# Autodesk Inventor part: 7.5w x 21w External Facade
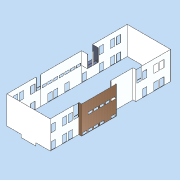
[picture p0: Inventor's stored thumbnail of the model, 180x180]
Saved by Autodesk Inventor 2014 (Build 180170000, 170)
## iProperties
Created: 2012-07
Part Number: 7.5w x 21w External Facade
Document SubType Name: Modeling
Designer: david.appleford
Mass: 7.63356e+06 g
Surface Area: 7.71188e+06 cm^2
Volume: 7.63356e+06 cm^3
Density: 1 g/cm^3
Cost Center: REF
Description: External Facade
Material: Generic
Appearance: Snow
Justset: False
Author: david.appleford
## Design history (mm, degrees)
sketch "Sketch1"
  geometry: L1 (6, -567)-(6, 565) reference; L2 (-78, 649)-(-600, 649) reference; L3 (-9140, -25051)-(-8008, -25051) reference; L4 (-9224, -23835)-(-9224, -24967) reference; L5 (616, -12767)-(616, -11635) reference; L6 (532, -11551)-(424, -11551) reference; L7 (616, -18867)-(616, -17735) reference; L8 (10, -18951)-(532, -18951) reference; L9 (-600, -6751)-(-78, -6751) reference; L10 (-604, -7887)-(-604, -6755) reference; L11 (-492, -11551)-(418, -11551) reference; L12 (-9224, -25051)-(6, -25051); L13 (6, 649)-(-9224, 649); L14 (-9224, 649)-(-9224, -25051); L15 (6, -6751)-(-604, -6751); L16 (-604, -6751)-(-604, -11551); L17 (-604, -11551)-(6, -11551); L18 (6, -11551)-(616, -11551); L19 (616, -11551)-(616, -18951); L20 (616, -18951)-(6, -18951); L21 (6, -25051)-(6, -18951); L22 (6, -6751)-(6, 649); L23 (-584, -11531)-(-584, -6771); L24 (-584, -6771)-(26, -6771); L25 (26, -6771)-(26, 669); L26 (26, 669)-(-9244, 669); L27 (-9244, 669)-(-9244, -25071); L28 (-9244, -25071)-(26, -25071); L29 (26, -25071)-(26, -18971); L30 (26, -18971)-(636, -18971); L31 (636, -18971)-(636, -11531); L32 (636, -11531)-(6, -11531); L33 (6, -11531)-(-584, -11531); 1 further point
  constraints: 44 end point, 3 collinear, 1 point on line, 10 other
  dimensions: "d0" = 20 distance between parallel lines of L13 L26
  node "Reference1"
  node "Reference2"
  node "Reference3"
  node "Reference4"
  node "Reference5"
  node "Reference6"
  node "Reference7"
  node "Reference8"
  node "Reference9"
  node "Reference10"
  node "Reference11"
workplane "Work Plane1"
extrude "Extrusion1" new body sketch "Sketch1" stored distance "d1" = 10; taper "d2" = 0 deg
sketch "Sketch2"
  geometry: L1 (2668, 6015)-(2668, 5085) reference; L2 (2668, 5085)-(1138, 5085) reference; L3 (1138, 6015)-(2668, 6015) reference; L4 (1138, 5085)-(1138, 6015) reference; L5 (2668, 4795)-(2668, 3865) reference; L6 (1138, 4795)-(2668, 4795) reference; L7 (2668, 3865)-(1138, 3865) reference; L8 (1138, 3865)-(1138, 4795) reference; L9 (2668, 2355)-(2668, 1425) reference; L10 (1138, 2355)-(2668, 2355) reference; L11 (2668, 1425)-(1138, 1425) reference; L12 (1138, 1425)-(1138, 2355) reference; L13 (2664, 1135)-(2664, 205) reference; L14 (2184, 1135)-(2664, 1135) reference; L15 (2664, 205)-(2184, 205) reference; L16 (2184, 205)-(2184, 1135) reference; L17 (2111, 205)-(2111, 1141) reference; L18 (77, 205)-(2111, 205) reference; L19 (2111, 1141)-(77, 1141) reference; L20 (5877, 6015)-(5877, 5085) reference; L21 (4347, 6015)-(5877, 6015) reference; L22 (5877, 5085)-(4347, 5085) reference; L23 (4347, 5085)-(4347, 6015) reference; L24 (4347, 3865)-(4347, 4795) reference; L25 (4347, 4795)-(5877, 4795) reference; L26 (5877, 3865)-(4347, 3865) reference; L27 (5877, 4795)-(5877, 3865) reference; L28 (5877, 2355)-(5877, 1425) reference; L29 (5877, 1425)-(4347, 1425) reference; L30 (4347, 2355)-(5877, 2355) reference; L31 (4347, 1425)-(4347, 2355) reference; L32 (5877, -13505)-(5877, -14435) reference; L33 (5877, -14435)-(4347, -14435) reference; L34 (4347, -13505)-(5877, -13505) reference; L35 (4347, -14435)-(4347, -13505) reference; L36 (4347, -14725)-(5877, -14725) reference; L37 (5877, -14725)-(5877, -15655) reference; L38 (5877, -15655)-(4347, -15655) reference; L39 (4347, -15655)-(4347, -14725) reference; L40 (4347, -15945)-(5877, -15945) reference; L41 (5877, -15945)-(5877, -16875) reference; L42 (5877, -16875)-(4347, -16875) reference; L43 (4347, -16875)-(4347, -15945) reference; L44 (5877, -17165)-(5877, -18095) reference; L45 (4347, -17165)-(5877, -17165) reference; L46 (5877, -18095)-(4347, -18095) reference; L47 (4347, -18095)-(4347, -17165) reference; L48 (2668, -17165)-(2668, -18095) reference; L49 (2668, -18095)-(1138, -18095) reference; L50 (1138, -17165)-(2668, -17165) reference; L51 (1138, -18095)-(1138, -17165) reference; L52 (2668, -14725)-(2668, -15655) reference; L53 (1138, -14725)-(2668, -14725) reference; L54 (2668, -15655)-(1138, -15655) reference; L55 (1138, -15655)-(1138, -14725) reference; L56 (1138, -14435)-(1138, -13505) reference; L57 (2668, -13505)-(2668, -14435) reference; L58 (2668, -14435)-(1138, -14435) reference; L59 (1138, -13505)-(2668, -13505) reference; L60 (2664, -12285)-(2664, -13215) reference; L61 (2664, -13215)-(2184, -13215) reference; L62 (2184, -13215)-(2184, -12285) reference; L63 (2184, -12285)-(2664, -12285) reference; L64 (2111, -13215)-(2111, -12279) reference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; 1 further point
  constraints: 18 end point, 3 point on line
extrude "Extrusion2" cut sketch "Sketch2" distance "d3" = 20; taper "d4" = 0 deg
sketch "Sketch3"
  geometry: L1 (5873, 6305)-(5393, 6305) reference; L2 (5873, 7235)-(5873, 6305) reference; L3 (5393, 7235)-(5873, 7235) reference; L4 (5393, 6305)-(5393, 7235) reference; L5 (5393, 6015)-(5873, 6015) reference; L6 (5873, 6015)-(5873, 5085) reference; L7 (5873, 5085)-(5393, 5085) reference; L8 (5393, 5085)-(5393, 6015) reference; L9 (5393, 4795)-(5873, 4795) reference; L10 (5873, 4795)-(5873, 3865) reference; L11 (5873, 3865)-(5393, 3865) reference; L12 (5393, 3865)-(5393, 4795) reference; L13 (5393, 3575)-(5873, 3575) reference; L14 (5873, 3575)-(5873, 2645) reference; L15 (5873, 2645)-(5393, 2645) reference; L16 (5393, 2645)-(5393, 3575) reference; L17 (5393, 2355)-(5873, 2355) reference; L18 (5873, 2355)-(5873, 1425) reference; L19 (5873, 1425)-(5393, 1425) reference; L20 (5393, 1425)-(5393, 2355) reference; L21 (5393, 1135)-(5873, 1135) reference; L22 (5873, 1135)-(5873, 205) reference; L23 (5873, 205)-(5393, 205) reference; L24 (5393, 205)-(5393, 1135) reference; L25 (2184, 7235)-(2664, 7235) reference; L26 (2664, 7235)-(2664, 6305) reference; L27 (2664, 6305)-(2184, 6305) reference; L28 (2184, 6305)-(2184, 7235) reference; L29 (2184, 6015)-(2664, 6015) reference; L30 (2664, 6015)-(2664, 5085) reference; L31 (2664, 5085)-(2184, 5085) reference; L32 (2184, 5085)-(2184, 6015) reference; L33 (2664, 4795)-(2664, 3865) reference; L34 (2184, 4795)-(2664, 4795) reference; L35 (2184, 3865)-(2184, 4795) reference; L36 (2664, 3865)-(2184, 3865) reference; L37 (2184, 3575)-(2664, 3575) reference; L38 (2664, 3575)-(2664, 2645) reference; L39 (2664, 2645)-(2184, 2645) reference; L40 (2184, 2645)-(2184, 3575) reference; L41 (2184, 2355)-(2664, 2355) reference; L42 (2664, 2355)-(2664, 1425) reference; L43 (2664, 1425)-(2184, 1425) reference; L44 (2184, 1425)-(2184, 2355) reference; 1 further point
extrude "Extrusion3" cut sketch "Sketch3" distance "d5" = 20; taper "d6" = 0 deg
sketch "Sketch4"
  geometry: L1 (85, 2664)-(1015, 2664) reference; L2 (85, 2184)-(85, 2664) reference; L3 (1015, 2664)-(1015, 2184) reference; L4 (1015, 2184)-(85, 2184) reference; L5 (1015, 2111)-(79, 2111) reference; L6 (79, 2111)-(79, 77) reference; L7 (1015, 77)-(1015, 2111) reference; L8 (1015, 77)-(79, 77); L9 (1116, 66.469)-(1116, 78) reference; L10 (-16, 78)-(1116, 78) reference; L11 (-16, 66.469)-(-16, 78) reference; L12 (-16, 66.469)-(1116, 66.469) reference; L13 (1116, -6)-(1116, 47.141) reference; L14 (-16, 47.141)-(1116, 47.141) reference; L15 (-16, -6)-(-16, 47.141) reference; L16 (-16, -6)-(1116, -6) reference; L17 (1116, -6)-(-16, -6); L18 (-16, -6)-(-16, 78); L19 (1116, 78)-(1116, -6); L20 (-16, 78)-(79, 78); L21 (1015, 78)-(1116, 78); 1 further point
  constraints: 12 end point, 2 point on line
extrude "Extrusion4" cut sketch "Sketch4" distance "d7" = 20; taper "d8" = 0 deg
sketch "Sketch5"
  geometry: L1 (-5877, 1425)-(-5877, 2355) reference; L2 (-4347, 1425)-(-5877, 1425) reference; L3 (-5877, 2355)-(-4347, 2355) reference; L4 (-4347, 2355)-(-4347, 1425); L5 (-5877, 2645)-(-5877, 3575) reference; L6 (-4347, 2645)-(-5877, 2645) reference; L7 (-5877, 3575)-(-4347, 3575) reference; L8 (-4347, 3575)-(-4347, 2645) reference; L9 (-5877, 5085)-(-5877, 6015) reference; L10 (-4347, 5085)-(-5877, 5085) reference; L11 (-5877, 6015)-(-4347, 6015) reference; L12 (-4347, 6015)-(-4347, 5085) reference; L13 (-2668, 1425)-(-2668, 2355) reference; L14 (-1138, 1425)-(-2668, 1425) reference; L15 (-2668, 2355)-(-1138, 2355) reference; L16 (-1138, 2355)-(-1138, 1425) reference; L17 (-1138, 2645)-(-2668, 2645) reference; L18 (-2668, 2645)-(-2668, 3575) reference; L19 (-2668, 3575)-(-1138, 3575) reference; L20 (-1138, 3575)-(-1138, 2645) reference; L21 (-2668, 5085)-(-2668, 6015) reference; L22 (-1138, 5085)-(-2668, 5085) reference; L23 (-2668, 6015)-(-1138, 6015) reference; L24 (-1138, 6015)-(-1138, 5085) reference; L25 (-2664, 6305)-(-2664, 7235) reference; L26 (-2664, 7235)-(-2184, 7235) reference; L27 (-2184, 7235)-(-2184, 6305) reference; L28 (-2184, 6305)-(-2664, 6305) reference; L29 (-2184, 7525)-(-2664, 7525) reference; L30 (-2664, 7525)-(-2664, 8455) reference; L31 (-2664, 8455)-(-2184, 8455) reference; L32 (-2184, 8455)-(-2184, 7525) reference; L33 (-2664, 8745)-(-2664, 9675) reference; L34 (-2664, 9675)-(-2184, 9675) reference; L35 (-2184, 9675)-(-2184, 8745) reference; L36 (-2184, 8745)-(-2664, 8745) reference; L37 (-2184, 9965)-(-2664, 9965) reference; L38 (-2664, 9965)-(-2664, 10895) reference; L39 (-2664, 10895)-(-2184, 10895) reference; L40 (-2184, 10895)-(-2184, 9965) reference; L41 (-2664, 12405)-(-2664, 13335) reference; L42 (-2664, 13335)-(-2184, 13335) reference; L43 (-2184, 13335)-(-2184, 12405) reference; L44 (-2184, 12405)-(-2664, 12405) reference; L45 (-2664, 11185)-(-2664, 12115) reference; L46 (-2184, 11185)-(-2664, 11185) reference; L47 (-2664, 12115)-(-2184, 12115) reference; L48 (-2184, 12115)-(-2184, 11185) reference; L49 (-2664, 13625)-(-2664, 14555) reference; L50 (-2664, 14555)-(-2184, 14555) reference; L51 (-2184, 14555)-(-2184, 13625) reference; L52 (-2184, 13625)-(-2664, 13625) reference; L53 (-2664, 14845)-(-2664, 15775) reference; L54 (-2184, 14845)-(-2664, 14845) reference; L55 (-2664, 15775)-(-2184, 15775) reference; L56 (-2184, 15775)-(-2184, 14845) reference; L57 (-2668, 19725)-(-2668, 20655) reference; L58 (-1138, 19725)-(-2668, 19725) reference; L59 (-2668, 20655)-(-1138, 20655) reference; L60 (-1138, 20655)-(-1138, 19725) reference; L61 (-5877, 16065)-(-5877, 16995) reference; L62 (-4347, 16065)-(-5877, 16065) reference; L63 (-5877, 16995)-(-4347, 16995) reference; L64 (-4347, 16995)-(-4347, 16065) reference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; 1 further point
  constraints: 14 end point, 2 point on line
extrude "Extrusion5" cut sketch "Sketch5" distance "d9" = 20; taper "d10" = 0 deg
sketch "Sketch6"
  geometry: L1 (5870, 15960)-(3213, 15960) reference; L2 (3213, 18320)-(5870, 18320) reference; L3 (3212, 17190)-(3212, 18310) reference; L4 (3232, 15980)-(5948, 15980); L5 (5948, 15980)-(5948, 18300); L6 (5948, 18300)-(3232, 18300); L7 (3232, 18300)-(3232, 15980); L8 (5870, 17184)-(3213, 17184) reference; L9 (3213, 19536)-(5870, 19536) reference; L10 (5948, 25740)-(5948, 7336) reference; 1 further point
  constraints: 8 end point, 1 collinear
  dimensions: "d11" = 20 distance between parallel lines of L7 L3; "d16" = 20 distance between parallel lines of L4 L1; "d17" = 20 distance between parallel lines of L2 L6
extrude "Extrusion7" cut sketch "Sketch6" distance "d18" = 20; taper "d19" = 0 deg
sketch "Sketch7"
  geometry: L1 (-8004, -6755)-(-8004, -6863) reference; L2 (-8008, -9107)-(-8008, -7975) reference; L3 (-7998, -9117)-(-7930, -9117) reference; L4 (-7930, -8542)-(-7930, -9117) reference; L5 (-7930, -8542)-(-7998, -8542) reference; L6 (-7998, -8542)-(-7998, -9117) reference; L7 (-9244, -6771)-(-9224, -6771) reference; L8 (-9224, -9091)-(-9244, -9091) reference; L9 (-9224, -6771)-(-8024, -6771); L10 (-8024, -6771)-(-8024, -9091); L11 (-8024, -9091)-(-9224, -9091); L12 (-9224, -9111)-(-8004, -9111); L13 (-8004, -9111)-(-8004, -6751); L14 (-8004, -6751)-(-9224, -6751); L15 (-9224, -9111)-(-9224, -9091); L16 (-9224, -6771)-(-9224, -6751); 1 further point
  constraints: 16 end point, 2 collinear, 1 other
  dimensions: "d20" = 20 distance between parallel lines of L1 L10; "d23" = 20 distance between parallel lines of L11 L12; "d24" = 20 distance between parallel lines of L14 L9 (derived)
extrude "Extrusion8" join sketch "Sketch7" stored distance "d21" = 20; taper "d22" = 0 deg
sketch "Sketch8"
  geometry: L1 (1220, 0)-(20, 0) reference; L2 (1220, 2320)-(1220, 0) reference; L3 (20, 2320)-(20, 0) reference; L4 (0, 2320)-(1220, 2320) reference; L5 (0, 0)-(0, 2320) reference; 1 further point
extrude "Extrusion9" join sketch "Sketch8" distance "d25" = 20; taper "d26" = 0 deg
sketch "Sketch9"
  geometry: L1 (-2664, 85)-(-2664, 1015) reference; L2 (-2664, 1015)-(-2184, 1015) reference; L3 (-2184, 1015)-(-2184, 85) reference; L4 (-2184, 85)-(-2664, 85) reference; L5 (-2664, 1305)-(-2664, 2235) reference; L6 (-2184, 1305)-(-2664, 1305) reference; L7 (-2664, 2235)-(-2184, 2235) reference; L8 (-2184, 2235)-(-2184, 1305) reference; L9 (-2111, 1015)-(-2111, 79) reference; L10 (-77, 1015)-(-2111, 1015) reference; L11 (-2111, 79)-(-77, 79) reference; L12 (-2111, 2235)-(-2111, 1299) reference; L13 (-2111, 1299)-(-77, 1299) reference; L14 (-77, 2235)-(-2111, 2235) reference; L15 (-77, 79)-(-77, 1015); L16 (-77, 1299)-(-77, 2235); L17 (-78, -16)-(-78, 1116) reference; L18 (0, 2320)-(0, 0) reference; L19 (-78, -16)-(0, -16); L20 (0, -16)-(0, 2320); L21 (0, 2320)-(-78, 2320); L22 (-78, 2320)-(-78, 2235); L23 (-78, 1299)-(-78, -16); L24 (-66.469, 1116)-(-78, 1116) reference; L25 (-66.469, 1204)-(-78, 1204) reference; L26 (-78, 1116)-(0, 1116); L27 (-78, 1204)-(0, 1204); 1 further point
  constraints: 18 end point, 4 point on line
extrude "Extrusion10" cut sketch "Sketch9" distance "d27" = 20; taper "d28" = 0 deg
sketch "Sketch10"
  geometry: L1 (3076, 6027)-(3144, 6027) reference; L2 (3144, 6568)-(3144, 6027) reference; L3 (3144, 6568)-(3076, 6568) reference; L4 (3076, 6568)-(3076, 6027) reference; L5 (6126, 6026)-(6194, 6026) reference; L6 (6194, 6568)-(6194, 6026) reference; L7 (6194, 6568)-(6126, 6568) reference; L8 (6126, 6568)-(6126, 6026) reference; L9 (6250, 6558)-(6250, 6636) reference; L10 (6250, 6636)-(3076, 6636) reference; L11 (3076, 6636)-(3076, 6558) reference; L12 (3076, 6558)-(6250, 6558) reference; L13 (0, 5948)-(9270, 5948) reference; L14 (0, 0)-(0, 5948) reference; L15 (9270, 0)-(0, 0) reference; L16 (9270, 0)-(9270, 5948) reference; L17 (3076, 6558)-(6194, 6558); L18 (6194, 6558)-(6194, 5948); L19 (6194, 5948)-(3076, 5948); L20 (3076, 5948)-(3076, 6558); 1 further point
  constraints: 8 end point, 1 point on line
extrude "Extrusion11" join sketch "Sketch10" distance "d29" = 20; taper "d30" = 0 deg
sketch "Sketch11"
  geometry: L1 (9270, -5948)-(0, -5948) reference; L2 (9270, 0)-(9270, -5948) reference; L3 (0, 0)-(9270, 0) reference; L4 (0, 0)-(0, -5948) reference; L5 (6194, -6027)-(6126, -6027) reference; L6 (6126, -6568)-(6126, -6027) reference; L7 (6126, -6568)-(6194, -6568) reference; L8 (6194, -6568)-(6194, -6027) reference; L9 (6194, -6636)-(6194, -6558) reference; L10 (6194, -6558)-(3020, -6558) reference; L11 (3020, -6558)-(3020, -6636) reference; L12 (3020, -6636)-(6194, -6636) reference; L13 (3076, -6568)-(3144, -6568) reference; L14 (3144, -6026)-(3144, -6568) reference; L15 (3144, -6026)-(3076, -6026) reference; L16 (3076, -6026)-(3076, -6568) reference; L17 (6194, -6558)-(3076, -6558); L18 (3076, -6558)-(3076, -5948); L19 (3076, -5948)-(6194, -5948); L20 (6194, -5948)-(6194, -6558); 1 further point
  constraints: 8 end point, 1 point on line
extrude "Extrusion12" join sketch "Sketch11" distance "d31" = 20; taper "d32" = 0 deg
sketch "Sketch13"
  geometry: L1 (0, 7235)-(3284, 7235); L2 (3284, 7235)-(3284, 7236); L3 (3284, 7236)-(0, 7236); L4 (0, 7236)-(0, 7235); L5 (0, 15979)-(3232, 15979); L6 (3232, 15979)-(3232, 15980); L7 (3232, 15980)-(0, 15980); L8 (0, 15980)-(0, 15979); L9 (3284, 6305)-(3284, 7235) reference; L10 (0, 0)-(0, 25740) reference; L11 (3232, 15980)-(3232, 18300) reference; L12 (3764, 7235)-(3764, 6305) reference; L13 (3837, 6299)-(3837, 7235) reference; L14 (3764, 7235)-(3837, 7235); L15 (3837, 7235)-(3837, 7236); L16 (3837, 7236)-(3764, 7236); L17 (3764, 7236)-(3764, 7235); 1 further point
  constraints: 24 end point, 3 collinear
  dimensions: "d35" = 1 distance between parallel lines of L3 L1; "d36" = 1 distance between parallel lines of L7 L5
extrude "Extrusion14" cut sketch "Sketch13" distance "d37" = 1; taper "d38" = 0 deg
body "Solid1"
node "Reference12"
node "Reference13"
node "Reference14"
node "Reference15"
node "Reference16"
node "Reference17"
node "Reference18"
node "Reference19"
node "Reference20"
node "Reference21"
node "Reference22"
node "Reference23"
node "Reference24"
node "Reference25"
node "Reference26"
node "Reference27"
node "Reference28"
node "Reference29"
node "Reference30"
node "Reference31"
node "Reference32"
node "Reference33"
node "Reference34"
node "Reference35"
node "Reference36"
node "Reference37"
node "Reference38"
node "Reference39"
node "Reference40"
node "Reference41"
node "Reference42"
node "Reference43"
node "Reference44"
node "Reference45"
node "Reference46"
node "Reference47"
node "Reference48"
node "Reference49"
node "Reference50"
node "Reference51"
node "Reference52"
node "Reference53"
node "Reference54"
node "Reference55"
node "Reference56"
node "Reference57"
node "Reference58"
node "Reference59"
node "Reference60"
node "Reference61"
node "Reference62"
node "Reference63"
node "Reference64"
node "Reference65"
node "Reference66"
node "Reference67"
node "Reference68"
node "Reference69"
node "Reference70"
node "Reference71"
node "Reference72"
node "Reference73"
node "Reference74"
node "Reference75"
node "Reference76"
node "Reference77"
node "Reference78"
node "Reference79"
node "Reference80"
node "Reference81"
node "Reference82"
node "Reference83"
node "Reference84"
node "Reference85"
node "Reference86"
node "Reference87"
node "Reference88"
node "Reference89"
node "Reference90"
node "Reference91"
node "Reference92"
node "Reference93"
node "Reference94"
node "Reference95"
node "Reference96"
node "Reference97"
node "Reference98"
node "Reference99"
node "Reference100"
node "Reference101"
node "Reference102"
node "Reference103"
node "Reference104"
node "Reference105"
node "Reference106"
node "Reference107"
node "Reference108"
node "Reference109"
node "Reference110"
node "Reference111"
node "Reference112"
node "Reference113"
node "Reference114"
node "Reference115"
node "Reference116"
node "Reference117"
node "Reference118"
node "Reference119"
node "Reference120"
node "Reference121"
node "Reference122"
node "Reference123"
node "Reference124"
node "Reference125"
node "Reference126"
node "Reference127"
node "Reference128"
node "Reference129"
node "Reference130"
node "Reference131"
node "Reference132"
node "Reference133"
node "Reference134"
node "Reference135"
node "Reference136"
node "Reference137"
node "Reference138"
node "Reference139"
node "Reference140"
node "Reference141"
node "Reference142"
node "Reference143"
node "Reference144"
node "Reference145"
node "Reference146"
node "Reference147"
node "Reference148"
node "Reference149"
node "Reference150"
node "Reference151"
node "Reference152"
node "Reference153"
node "Reference154"
node "Reference155"
node "Reference156"
node "Reference157"
node "Reference158"
node "Reference159"
node "Reference160"
node "Reference161"
node "Reference162"
node "Reference163"
node "Reference164"
node "Reference165"
node "Reference166"
node "Reference167"
node "Reference168"
node "Reference169"
node "Reference170"
node "Reference171"
node "Reference172"
node "Reference173"
node "Reference174"
node "Reference175"
node "Reference176"
node "Reference177"
node "Reference178"
node "Reference179"
node "Reference180"
node "Reference181"
node "Reference182"
node "Reference183"
node "Reference184"
node "Reference185"
node "Reference186"
node "Reference187"
node "Reference188"
node "Reference189"
node "Reference190"
node "Reference191"
node "Reference192"
node "Reference193"
node "Reference194"
node "Reference195"
node "Reference196"
node "Reference197"
node "Reference198"
node "Reference199"
node "Reference200"
node "Reference201"
node "Reference202"
node "Reference203"
node "Reference204"
node "Reference205"
node "Reference206"
node "Reference207"
node "Reference208"
node "Reference209"
node "Reference210"
node "Reference211"
node "Reference212"
node "Reference213"
node "Reference214"
node "Reference215"
node "Reference216"
node "Reference217"
node "Reference218"
node "Reference219"
node "Reference220"
node "Reference221"
node "Reference222"
node "Reference223"
node "Reference224"
node "Reference225"
node "Reference226"
node "Reference227"
node "Reference228"
node "Reference229"
node "Reference230"
node "Reference231"
node "Reference232"
node "Reference233"
node "Reference234"
node "Reference235"
node "Reference236"
node "Reference237"
node "Reference238"
node "Reference239"
node "Reference240"
node "Reference241"
node "Reference242"
node "Reference243"
node "Reference244"
node "Reference245"
node "Reference246"
node "Reference247"
node "Reference248"
node "Reference249"
node "Reference250"
node "Reference251"
node "Reference252"
node "Reference253"
node "Reference254"
node "Reference255"
node "Reference256"
node "Reference257"
node "Reference258"
node "Reference259"
node "Reference260"
node "Projected Loop1"
node "Projected Loop2"
node "Reference261"
node "Reference262"
node "Reference263"
